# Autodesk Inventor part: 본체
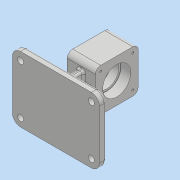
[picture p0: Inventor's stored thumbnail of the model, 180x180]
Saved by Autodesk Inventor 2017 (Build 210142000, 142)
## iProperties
Part Number: 본체
Material: 일반
Document SubType Name: Modeling
Designer: 7-1
Density: 1 g/cm^3
Appearance: 기본값
Author: 7-1
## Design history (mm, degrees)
sketch "스케치2"
  geometry: L1 (-32, 32)-(32, 32); L2 (32, 32)-(32, -32); L3 (32, -32)-(-32, -32); L4 (-32, -32)-(-32, 32); L5 (-32, 32)-(32, -32); L6 (32, 32)-(-32, -32); 1 further point
  constraints: 12 end point, 2 midpoint, 2 parallel, 1 horizontal, 1 perpendicular
  dimensions: "d0" = 64 distance of L2.end L3.end; "d1" = 64 distance of L1.end L2.end
extrude "돌출1" new body sketch "스케치2" stored distance "d2" = 42; taper "d3" = 0 deg
sketch "스케치3"
  geometry: C1 r 21 at (0, 0); 1 further point
  constraints: 1 centre point, 1 coincident
  dimensions: "d4" = 42 diameter of C1
extrude "돌출2" cut sketch "스케치3" distance "d5" = 15; taper "d6" = 0 deg
sketch "스케치4"
  geometry: C1 r 18 at (0, 0); 1 further point
  constraints: 1 centre point, 1 coincident
  dimensions: "d7" = 36 diameter of C1
extrude "돌출3" cut sketch "스케치4" stored distance "d8" = 15; taper "d9" = 0 deg
sketch "스케치5"
  geometry: C1 r 21 at (0, 0); 1 further point
  constraints: 1 centre point, 1 coincident
  dimensions: "d10" = 42 diameter of C1
extrude "돌출4" cut sketch "스케치5" distance "d11" = 15; taper "d12" = 0 deg
fillet "모깎기1" dims "d13" = 8
sketch "스케치6"
  geometry: A1 r 8 centre (-24, 24) between (-24, 32) and (-32, 24) reference; A2 r 8 centre (-24, -24) between (-32, -24) and (-24, -32) reference; A3 r 8 centre (24, -24) between (24, -32) and (32, -24) reference; A4 r 8 centre (24, 24) between (32, 24) and (24, 32) reference; 5 further points
  constraints: 4 coincident
hole "구멍1" sketch "스케치6" at (-24, -24), (24, -24), (24, 24), (-24, 24) diameter "d14" = 3.242; stored, may be unused: countersink angle "d18" = 90 deg, drill point angle "d20" = 118 deg; dims "d15" = 8, "d16" = 4, "d17" = 2, "d19" = 10
node "작업 평면1"
sketch "스케치7"
  geometry: L1 (-21, 24)-(21, 24) reference; L2 (-21, -24)-(-21, 24) reference; L3 (21, -24)-(-21, -24) reference; L4 (21, 24)-(21, -24) reference; L5 (65, -62)-(-65, -62); L6 (-65, -62)-(-65, 36); L7 (-65, 36)-(65, 36); L8 (65, 36)-(65, -62); 2 further points
  constraints: 8 end point, 2 parallel, 1 horizontal, 1 midpoint, 1 perpendicular, 1 vertical alignment
  dimensions: "d22" = 98 distance of L5.end L6.end; "d23" = 130 distance of L5.start L5.end; "d24" = 62 distance from line of point (0, 0) L5
extrude "돌출5" join sketch "스케치7" distance "d25" = 10; taper "d26" = 0 deg
sketch "스케치8"
  geometry: L1 (-17, 4)-(-4, 4); L2 (17, 4)-(17, -4); L3 (17, -4)-(4, -4); L4 (-17, -4)-(-17, 4); L5 (-4, 20)-(4, 20); L6 (4, 20)-(4, 4); L7 (4, -20)-(-4, -20); L8 (-4, -20)-(-4, -4); L9 (-4, -4)-(-17, -4); L10 (4, -4)-(-4, -4); L11 (4, -4)-(4, -20); L12 (4, 4)-(4, -4); L13 (4, 4)-(17, 4); L14 (-4, 4)-(4, 4); L15 (-4, 4)-(-4, 20); L16 (-4, -4)-(-4, 4); 5 further points
  constraints: 32 end point, 20 parallel, 6 perpendicular, 4 horizontal, 2 horizontal alignment, 2 midpoint, 2 vertical alignment
  dimensions: "d27" = 34 distance of L2.end L4.start; "d28" = 8 distance of L2.start L2.end; "d29" = 8 distance of L7.start L7.end; "d30" = 40 distance of L5.end L7.start; "d31" = 17 distance from line of L4 point (0, 0); "d32" = 20 distance from line of point (0, 0) L5; "d33" = 4 distance of point (0, 0) point (-4, 0); "d34" = 4 distance of point (0, 0) point (0, 4)
extrude "돌출6" join sketch "스케치8" stored distance "d35" = 10; taper "d36" = 0 deg
fillet "모깎기2" dims "d37" = 12
sketch "스케치9"
  geometry: A1 r 12 centre (-53, 50) between (-53, 62) and (-65, 50) reference; A2 r 12 centre (-53, -24) between (-65, -24) and (-53, -36) reference; A3 r 12 centre (53, -24) between (53, -36) and (65, -24) reference; A4 r 12 centre (53, 50) between (65, 50) and (53, 62) reference; 5 further points
  constraints: 4 coincident
hole "구멍2" sketch "스케치9" at (-53, 50), (-53, -24), (53, -24), (53, 50) diameter "d38" = 9; stored, may be unused: countersink angle "d42" = 90 deg, drill point angle "d44" = 0 deg; dims "d39" = 8, "d40" = 4, "d41" = 2, "d43" = 10
fillet "모깎기3" dims "d45" = 3
fillet "모깎기4" dims "d46" = 3
fillet "모깎기5" dims "d47" = 0.3
sketch "스케치10"
  geometry: L1 (65, 50)-(65, -24) reference; L2 (53, -36)-(-53, -36) reference; L3 (-65, -24)-(-65, 50) reference; L4 (-53, 62)-(53, 62) reference; C1 r 4.5 at (53, -24) reference; C2 r 4.5 at (-53, 50) reference; C3 r 4.5 at (-53, -24) reference; C4 r 4.5 at (53, 50) reference; A1 r 12 centre (53, 50) between (65, 50) and (53, 62) reference; A2 r 12 centre (53, -24) between (53, -36) and (65, -24) reference; A3 r 12 centre (-53, -24) between (-65, -24) and (-53, -36) reference; A4 r 12 centre (-53, 50) between (-53, 62) and (-65, 50) reference; 2 further points
  constraints: 1 vertical alignment, 1 other
  dimensions: "d48" = 10 distance from line of L4 point (0, 52)
feature "엠보싱1" sketch "스케치10" dims "d49" = 0.5, "d50" = 0
node "솔리드1"
mirror "미러1"
node "투영된 루프1"
node "투영된 루프2"
